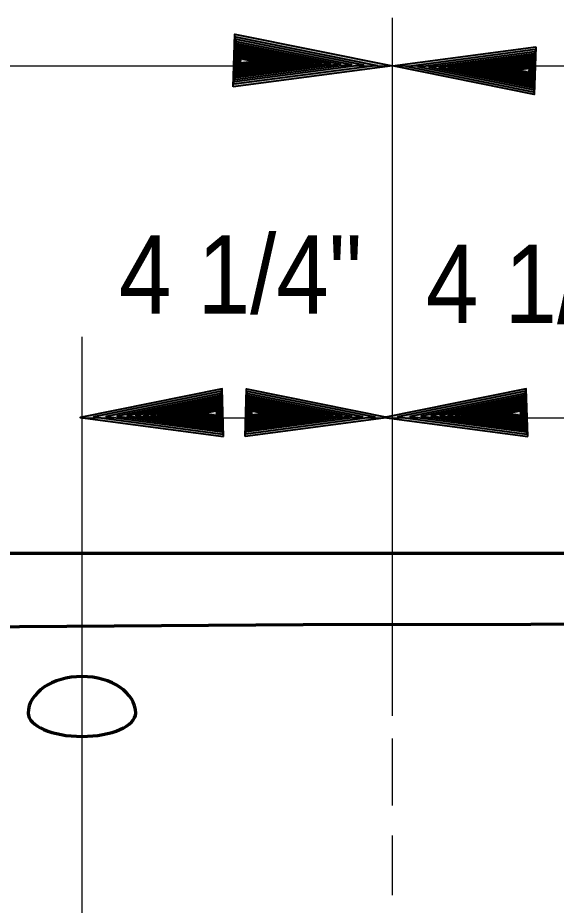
# Model space of a CAD drawing. Extents: x 895.6 to 930.4, y -2278.6 to -2254.7.
# Drawn here: x 917.544 to 918.427, y -2271.618 to -2270.162 of the extents above; entities that cross this region are included whole.
import ezdxf

# ---------------------------------------------------------------- set-up
doc = ezdxf.new("R2010")
doc.units = 0
doc.header["$LTSCALE"] = 0.051
doc.layers.add('1', color=7, linetype='Continuous', lineweight=70)
doc.layers.add('3', color=7, linetype='Continuous', lineweight=40)

msp = doc.modelspace()

# ---------------------------------------------------------------- hatches: boundary and pattern name
at = {"layer": '3'}
for points in [[(917.89717, -2270.27517), (917.90008, -2270.1885), (918.1585, -2270.24067), (918.1585, -2270.24067)], [(917.89842, -2270.27083), (917.90117, -2270.19283), (918.13367, -2270.23983), (918.13367, -2270.23983)], [(917.89967, -2270.26692), (917.902, -2270.19683), (918.11133, -2270.23917), (918.11133, -2270.23917)], [(917.90067, -2270.2635), (917.90283, -2270.20042), (918.09133, -2270.23842), (918.09133, -2270.23842)], [(917.90158, -2270.2605), (917.9035, -2270.20367), (918.07325, -2270.23783), (918.07325, -2270.23783)], [(917.90267, -2270.25758), (917.90425, -2270.2065), (918.057, -2270.23733), (918.057, -2270.23733)], [(917.90333, -2270.255), (917.90483, -2270.20908), (918.04225, -2270.23683), (918.04225, -2270.23683)], [(917.90417, -2270.25283), (917.90542, -2270.21142), (918.029, -2270.23633), (918.029, -2270.23633)], [(917.90458, -2270.25083), (917.90592, -2270.21342), (918.01725, -2270.23583), (918.01725, -2270.23583)], [(917.90533, -2270.24892), (917.90642, -2270.21517), (918.00642, -2270.2355), (918.00642, -2270.2355)], [(917.90575, -2270.24733), (917.90683, -2270.217), (917.99683, -2270.23525), (917.99683, -2270.23525)], [(917.90625, -2270.24575), (917.90717, -2270.21858), (917.98817, -2270.23483), (917.98817, -2270.23483)], [(917.90667, -2270.24442), (917.9075, -2270.21992), (917.98033, -2270.23467), (917.98033, -2270.23467)], [(918.39375, -2270.20958), (918.39108, -2270.28758), (918.1585, -2270.24067), (918.1585, -2270.24067)], [(918.39258, -2270.2135), (918.39017, -2270.28367), (918.18083, -2270.2415), (918.18083, -2270.2415)], [(918.3915, -2270.217), (918.38933, -2270.28017), (918.20092, -2270.24208), (918.20092, -2270.24208)], [(918.39058, -2270.22008), (918.38858, -2270.27683), (918.219, -2270.24267), (918.219, -2270.24267)], [(917.90717, -2270.24317), (917.90775, -2270.22117), (917.97342, -2270.23442), (917.97342, -2270.23442)], [(917.90742, -2270.24217), (917.90808, -2270.22225), (917.96717, -2270.23425), (917.96717, -2270.23425)], [(917.90783, -2270.24108), (917.90825, -2270.22325), (917.9615, -2270.23392), (917.9615, -2270.23392)], [(917.908, -2270.24017), (917.90858, -2270.22408), (917.95642, -2270.23375), (917.95642, -2270.23375)], [(917.90817, -2270.23933), (917.90867, -2270.22492), (917.95183, -2270.23358), (917.95183, -2270.23358)], [(917.90858, -2270.23892), (917.90883, -2270.22575), (917.94775, -2270.23358), (917.94775, -2270.23358)], [(917.90875, -2270.23833), (917.90917, -2270.2265), (917.94408, -2270.2335), (917.94408, -2270.2335)], [(917.90908, -2270.23783), (917.90942, -2270.22725), (917.94083, -2270.23367), (917.94083, -2270.23367)], [(917.90908, -2270.23725), (917.90942, -2270.22783), (917.93775, -2270.2335), (917.93775, -2270.2335)], [(917.90925, -2270.23675), (917.90958, -2270.22825), (917.935, -2270.23325), (917.935, -2270.23325)], [(917.90942, -2270.23633), (917.90967, -2270.22875), (917.93267, -2270.23333), (917.93267, -2270.23333)], [(918.38975, -2270.22275), (918.388, -2270.274), (918.23525, -2270.24317), (918.23525, -2270.24317)], [(918.38883, -2270.2255), (918.38733, -2270.27142), (918.24992, -2270.24375), (918.24992, -2270.24375)], [(918.38817, -2270.22775), (918.38683, -2270.26917), (918.26308, -2270.24417), (918.26308, -2270.24417)], [(918.38742, -2270.22967), (918.38633, -2270.267), (918.27508, -2270.2445), (918.27508, -2270.2445)], [(918.38708, -2270.23158), (918.38583, -2270.26525), (918.28567, -2270.24508), (918.28567, -2270.24508)], [(918.38642, -2270.23325), (918.38533, -2270.26358), (918.29542, -2270.24525), (918.29542, -2270.24525)], [(918.38592, -2270.23475), (918.38508, -2270.26192), (918.30408, -2270.24558), (918.30408, -2270.24558)], [(918.38558, -2270.23617), (918.38467, -2270.26058), (918.31175, -2270.24592), (918.31175, -2270.24592)], [(918.38517, -2270.23725), (918.38442, -2270.25933), (918.31892, -2270.24608), (918.31892, -2270.24608)], [(918.38467, -2270.23842), (918.38425, -2270.25825), (918.32508, -2270.24633), (918.32508, -2270.24633)], [(918.3845, -2270.23933), (918.38383, -2270.25725), (918.33075, -2270.24642), (918.33075, -2270.24642)], [(918.38417, -2270.24033), (918.38375, -2270.25642), (918.33583, -2270.24675), (918.33583, -2270.24675)], [(918.38392, -2270.24108), (918.3835, -2270.25567), (918.34042, -2270.24692), (918.34042, -2270.24692)], [(918.38383, -2270.24183), (918.38333, -2270.25483), (918.34458, -2270.24708), (918.34458, -2270.24708)], [(918.3835, -2270.24225), (918.38317, -2270.25408), (918.34817, -2270.24708), (918.34817, -2270.24708)], [(918.38325, -2270.24283), (918.38292, -2270.25342), (918.35142, -2270.24708), (918.35142, -2270.24708)], [(918.383, -2270.24317), (918.38267, -2270.25275), (918.35442, -2270.247), (918.35442, -2270.247)], [(918.383, -2270.24375), (918.38267, -2270.25225), (918.35725, -2270.24708), (918.35725, -2270.24708)], [(918.38283, -2270.24425), (918.3825, -2270.25183), (918.35958, -2270.24733), (918.35958, -2270.24733)], [(918.38267, -2270.2445), (918.3825, -2270.25133), (918.36183, -2270.24725), (918.36183, -2270.24725)], [(917.88167, -2270.84892), (917.879, -2270.77092), (917.64633, -2270.81783), (917.64633, -2270.81783)], [(917.91675, -2270.84892), (917.91942, -2270.77092), (918.15208, -2270.81783), (918.15208, -2270.81783)], [(918.38042, -2270.84892), (918.37775, -2270.77092), (918.14508, -2270.81783), (918.14508, -2270.81783)], [(917.88042, -2270.845), (917.87808, -2270.77483), (917.66875, -2270.817), (917.66875, -2270.817)], [(917.87942, -2270.8415), (917.87725, -2270.77842), (917.68883, -2270.81642), (917.68883, -2270.81642)], [(917.87842, -2270.83842), (917.8765, -2270.78167), (917.70692, -2270.81583), (917.70692, -2270.81583)], [(917.87767, -2270.83575), (917.87583, -2270.78458), (917.72317, -2270.81533), (917.72317, -2270.81533)], [(917.87667, -2270.83308), (917.87517, -2270.78708), (917.73783, -2270.81483), (917.73783, -2270.81483)], [(917.918, -2270.845), (917.92033, -2270.77483), (918.12967, -2270.817), (918.12967, -2270.817)], [(917.919, -2270.8415), (917.92117, -2270.77842), (918.10958, -2270.81642), (918.10958, -2270.81642)], [(917.92, -2270.83842), (917.92192, -2270.78167), (918.0915, -2270.81583), (918.0915, -2270.81583)], [(917.92075, -2270.83575), (917.92258, -2270.78458), (918.07525, -2270.81533), (918.07525, -2270.81533)], [(917.92175, -2270.83308), (917.92325, -2270.78708), (918.06058, -2270.81483), (918.06058, -2270.81483)], [(918.37917, -2270.845), (918.37683, -2270.77483), (918.1675, -2270.817), (918.1675, -2270.817)], [(918.37817, -2270.8415), (918.376, -2270.77842), (918.18758, -2270.81642), (918.18758, -2270.81642)], [(918.37717, -2270.83842), (918.37525, -2270.78167), (918.20567, -2270.81583), (918.20567, -2270.81583)], [(918.37642, -2270.83575), (918.37458, -2270.78458), (918.22192, -2270.81533), (918.22192, -2270.81533)], [(918.37542, -2270.83308), (918.37392, -2270.78708), (918.23658, -2270.81483), (918.23658, -2270.81483)], [(917.87608, -2270.83075), (917.87475, -2270.78933), (917.751, -2270.81433), (917.751, -2270.81433)], [(917.87533, -2270.82883), (917.87425, -2270.7915), (917.763, -2270.814), (917.763, -2270.814)], [(917.875, -2270.827), (917.87367, -2270.79333), (917.77358, -2270.8135), (917.77358, -2270.8135)], [(917.87433, -2270.82525), (917.87325, -2270.79492), (917.78325, -2270.81325), (917.78325, -2270.81325)], [(917.87383, -2270.82375), (917.87292, -2270.79658), (917.79192, -2270.81292), (917.79192, -2270.81292)], [(917.8735, -2270.82233), (917.87258, -2270.798), (917.79967, -2270.81258), (917.79967, -2270.81258)], [(917.873, -2270.82125), (917.87233, -2270.79917), (917.80683, -2270.81242), (917.80683, -2270.81242)], [(917.87258, -2270.82008), (917.87208, -2270.80025), (917.81292, -2270.81225), (917.81292, -2270.81225)], [(917.87233, -2270.81917), (917.87175, -2270.80125), (917.81867, -2270.81208), (917.81867, -2270.81208)], [(917.87208, -2270.81825), (917.87167, -2270.80208), (917.82375, -2270.81175), (917.82375, -2270.81175)], [(917.92233, -2270.83075), (917.92367, -2270.78933), (918.04742, -2270.81433), (918.04742, -2270.81433)], [(917.92308, -2270.82883), (917.92417, -2270.7915), (918.03542, -2270.814), (918.03542, -2270.814)], [(917.92342, -2270.827), (917.92475, -2270.79333), (918.02483, -2270.8135), (918.02483, -2270.8135)], [(917.92408, -2270.82525), (917.92517, -2270.79492), (918.01517, -2270.81325), (918.01517, -2270.81325)], [(917.92458, -2270.82375), (917.9255, -2270.79658), (918.0065, -2270.81292), (918.0065, -2270.81292)], [(917.92492, -2270.82233), (917.92583, -2270.798), (917.99875, -2270.81258), (917.99875, -2270.81258)], [(917.92542, -2270.82125), (917.92608, -2270.79917), (917.99158, -2270.81242), (917.99158, -2270.81242)], [(917.92583, -2270.82008), (917.92633, -2270.80025), (917.9855, -2270.81225), (917.9855, -2270.81225)], [(917.92608, -2270.81917), (917.92667, -2270.80125), (917.97975, -2270.81208), (917.97975, -2270.81208)], [(917.92633, -2270.81825), (917.92675, -2270.80208), (917.97467, -2270.81175), (917.97467, -2270.81175)], [(918.37483, -2270.83075), (918.3735, -2270.78933), (918.24975, -2270.81433), (918.24975, -2270.81433)], [(918.37408, -2270.82883), (918.373, -2270.7915), (918.26175, -2270.814), (918.26175, -2270.814)], [(918.37375, -2270.827), (918.37242, -2270.79333), (918.27233, -2270.8135), (918.27233, -2270.8135)], [(918.37308, -2270.82525), (918.372, -2270.79492), (918.282, -2270.81325), (918.282, -2270.81325)], [(918.37258, -2270.82375), (918.37167, -2270.79658), (918.29067, -2270.81292), (918.29067, -2270.81292)], [(918.37225, -2270.82233), (918.37133, -2270.798), (918.29842, -2270.81258), (918.29842, -2270.81258)], [(918.37175, -2270.82125), (918.37108, -2270.79917), (918.30558, -2270.81242), (918.30558, -2270.81242)], [(918.37133, -2270.82008), (918.37083, -2270.80025), (918.31167, -2270.81225), (918.31167, -2270.81225)], [(918.37108, -2270.81917), (918.3705, -2270.80125), (918.31742, -2270.81208), (918.31742, -2270.81208)], [(918.37083, -2270.81825), (918.37042, -2270.80208), (918.3225, -2270.81175), (918.3225, -2270.81175)], [(917.87183, -2270.81742), (917.87133, -2270.80283), (917.82833, -2270.81158), (917.82833, -2270.81158)], [(917.87167, -2270.81667), (917.87125, -2270.80367), (917.83242, -2270.8115), (917.83242, -2270.8115)], [(917.87133, -2270.81625), (917.87108, -2270.80442), (917.83608, -2270.8115), (917.83608, -2270.8115)], [(917.87117, -2270.81567), (917.87083, -2270.80508), (917.83933, -2270.81142), (917.83933, -2270.81142)], [(917.87092, -2270.81533), (917.87058, -2270.80575), (917.84233, -2270.81158), (917.84233, -2270.81158)], [(917.87092, -2270.81475), (917.87058, -2270.80625), (917.84508, -2270.81142), (917.84508, -2270.81142)], [(917.87075, -2270.81425), (917.87042, -2270.80667), (917.8475, -2270.81117), (917.8475, -2270.81117)], [(917.87058, -2270.814), (917.87033, -2270.80717), (917.84967, -2270.81125), (917.84967, -2270.81125)], [(917.92658, -2270.81742), (917.92708, -2270.80283), (917.97008, -2270.81158), (917.97008, -2270.81158)], [(917.92675, -2270.81667), (917.92717, -2270.80367), (917.966, -2270.8115), (917.966, -2270.8115)], [(917.92708, -2270.81625), (917.92733, -2270.80442), (917.96233, -2270.8115), (917.96233, -2270.8115)], [(917.92725, -2270.81567), (917.92758, -2270.80508), (917.95908, -2270.81142), (917.95908, -2270.81142)], [(917.9275, -2270.81533), (917.92783, -2270.80575), (917.95608, -2270.81158), (917.95608, -2270.81158)], [(917.9275, -2270.81475), (917.92783, -2270.80625), (917.95333, -2270.81142), (917.95333, -2270.81142)], [(917.92767, -2270.81425), (917.928, -2270.80667), (917.95092, -2270.81117), (917.95092, -2270.81117)], [(917.92783, -2270.814), (917.92808, -2270.80717), (917.94875, -2270.81125), (917.94875, -2270.81125)], [(918.37058, -2270.81742), (918.37008, -2270.80283), (918.32708, -2270.81158), (918.32708, -2270.81158)], [(918.37042, -2270.81667), (918.37, -2270.80367), (918.33117, -2270.8115), (918.33117, -2270.8115)], [(918.37008, -2270.81625), (918.36983, -2270.80442), (918.33483, -2270.8115), (918.33483, -2270.8115)], [(918.36992, -2270.81567), (918.36958, -2270.80508), (918.33808, -2270.81142), (918.33808, -2270.81142)], [(918.36967, -2270.81533), (918.36933, -2270.80575), (918.34108, -2270.81158), (918.34108, -2270.81158)], [(918.36967, -2270.81475), (918.36933, -2270.80625), (918.34383, -2270.81142), (918.34383, -2270.81142)], [(918.3695, -2270.81425), (918.36917, -2270.80667), (918.34625, -2270.81117), (918.34625, -2270.81117)], [(918.36933, -2270.814), (918.36908, -2270.80717), (918.34842, -2270.81125), (918.34842, -2270.81125)]]:
    msp.add_hatch(color=256, dxfattribs=at).paths.add_polyline_path(points)

# ---------------------------------------------------------------- linework, layer by layer
at = {"layer": '1', "lineweight": 25}
for p, q in [((918.1585, -2271.30775), (918.1585, -2270.16167)), ((915.22142, -2270.24067), (918.1585, -2270.24067)), ((918.1585, -2270.24067), (919.16992, -2270.24067)), ((917.64958, -2271.94067), (917.64958, -2270.68567)), ((917.64958, -2270.81817), (919.1535, -2270.81817)), ((918.1585, -2271.45492), (918.1585, -2271.34458)), ((918.1585, -2271.60208), (918.1585, -2271.504))]:
    msp.add_line(p, q, dxfattribs=at)
at = {"layer": '1'}
msp.add_line((919.14467, -2271.04083), (915.53433, -2271.04083), dxfattribs=at)
msp.add_lwpolyline([(919.14442, -2271.15792), (918.759, -2271.157), (918.012, -2271.15792), (917.23617, -2271.16342), (917.23658, -2271.1625)], dxfattribs=at)
for major_axis, ratio in [((-0.08819, 0), 0.679978), ((0.08819, 0), 0.434256)]:
    msp.add_ellipse((917.64926, -2271.30308), major_axis=major_axis, ratio=ratio, start_param=3.1415927, end_param=6.2831853, dxfattribs=at)
at = {"layer": '3'}
for points in [[(917.89717, -2270.27517), (917.90008, -2270.1885), (918.1585, -2270.24067), (918.1585, -2270.24067)], [(917.89842, -2270.27083), (917.90117, -2270.19283), (918.13367, -2270.23983), (918.13367, -2270.23983)], [(917.89967, -2270.26692), (917.902, -2270.19683), (918.11133, -2270.23917), (918.11133, -2270.23917)], [(917.90067, -2270.2635), (917.90283, -2270.20042), (918.09133, -2270.23842), (918.09133, -2270.23842)], [(917.90158, -2270.2605), (917.9035, -2270.20367), (918.07325, -2270.23783), (918.07325, -2270.23783)], [(917.90267, -2270.25758), (917.90425, -2270.2065), (918.057, -2270.23733), (918.057, -2270.23733)], [(917.90333, -2270.255), (917.90483, -2270.20908), (918.04225, -2270.23683), (918.04225, -2270.23683)], [(917.90417, -2270.25283), (917.90542, -2270.21142), (918.029, -2270.23633), (918.029, -2270.23633)], [(917.90458, -2270.25083), (917.90592, -2270.21342), (918.01725, -2270.23583), (918.01725, -2270.23583)], [(917.90533, -2270.24892), (917.90642, -2270.21517), (918.00642, -2270.2355), (918.00642, -2270.2355)], [(917.90575, -2270.24733), (917.90683, -2270.217), (917.99683, -2270.23525), (917.99683, -2270.23525)], [(917.90625, -2270.24575), (917.90717, -2270.21858), (917.98817, -2270.23483), (917.98817, -2270.23483)], [(917.90667, -2270.24442), (917.9075, -2270.21992), (917.98033, -2270.23467), (917.98033, -2270.23467)], [(918.39375, -2270.20958), (918.39108, -2270.28758), (918.1585, -2270.24067), (918.1585, -2270.24067)], [(918.39258, -2270.2135), (918.39017, -2270.28367), (918.18083, -2270.2415), (918.18083, -2270.2415)], [(918.3915, -2270.217), (918.38933, -2270.28017), (918.20092, -2270.24208), (918.20092, -2270.24208)], [(918.39058, -2270.22008), (918.38858, -2270.27683), (918.219, -2270.24267), (918.219, -2270.24267)], [(917.90717, -2270.24317), (917.90775, -2270.22117), (917.97342, -2270.23442), (917.97342, -2270.23442)], [(917.90742, -2270.24217), (917.90808, -2270.22225), (917.96717, -2270.23425), (917.96717, -2270.23425)], [(917.90783, -2270.24108), (917.90825, -2270.22325), (917.9615, -2270.23392), (917.9615, -2270.23392)], [(917.908, -2270.24017), (917.90858, -2270.22408), (917.95642, -2270.23375), (917.95642, -2270.23375)], [(917.90817, -2270.23933), (917.90867, -2270.22492), (917.95183, -2270.23358), (917.95183, -2270.23358)], [(917.90858, -2270.23892), (917.90883, -2270.22575), (917.94775, -2270.23358), (917.94775, -2270.23358)], [(917.90875, -2270.23833), (917.90917, -2270.2265), (917.94408, -2270.2335), (917.94408, -2270.2335)], [(917.90908, -2270.23783), (917.90942, -2270.22725), (917.94083, -2270.23367), (917.94083, -2270.23367)], [(917.90908, -2270.23725), (917.90942, -2270.22783), (917.93775, -2270.2335), (917.93775, -2270.2335)], [(917.90925, -2270.23675), (917.90958, -2270.22825), (917.935, -2270.23325), (917.935, -2270.23325)], [(917.90942, -2270.23633), (917.90967, -2270.22875), (917.93267, -2270.23333), (917.93267, -2270.23333)], [(918.38975, -2270.22275), (918.388, -2270.274), (918.23525, -2270.24317), (918.23525, -2270.24317)], [(918.38883, -2270.2255), (918.38733, -2270.27142), (918.24992, -2270.24375), (918.24992, -2270.24375)], [(918.38817, -2270.22775), (918.38683, -2270.26917), (918.26308, -2270.24417), (918.26308, -2270.24417)], [(918.38742, -2270.22967), (918.38633, -2270.267), (918.27508, -2270.2445), (918.27508, -2270.2445)], [(918.38708, -2270.23158), (918.38583, -2270.26525), (918.28567, -2270.24508), (918.28567, -2270.24508)], [(918.38642, -2270.23325), (918.38533, -2270.26358), (918.29542, -2270.24525), (918.29542, -2270.24525)], [(918.38592, -2270.23475), (918.38508, -2270.26192), (918.30408, -2270.24558), (918.30408, -2270.24558)], [(918.38558, -2270.23617), (918.38467, -2270.26058), (918.31175, -2270.24592), (918.31175, -2270.24592)], [(918.38517, -2270.23725), (918.38442, -2270.25933), (918.31892, -2270.24608), (918.31892, -2270.24608)], [(918.38467, -2270.23842), (918.38425, -2270.25825), (918.32508, -2270.24633), (918.32508, -2270.24633)], [(918.3845, -2270.23933), (918.38383, -2270.25725), (918.33075, -2270.24642), (918.33075, -2270.24642)], [(918.38417, -2270.24033), (918.38375, -2270.25642), (918.33583, -2270.24675), (918.33583, -2270.24675)], [(918.38392, -2270.24108), (918.3835, -2270.25567), (918.34042, -2270.24692), (918.34042, -2270.24692)], [(918.38383, -2270.24183), (918.38333, -2270.25483), (918.34458, -2270.24708), (918.34458, -2270.24708)], [(918.3835, -2270.24225), (918.38317, -2270.25408), (918.34817, -2270.24708), (918.34817, -2270.24708)], [(918.38325, -2270.24283), (918.38292, -2270.25342), (918.35142, -2270.24708), (918.35142, -2270.24708)], [(918.383, -2270.24317), (918.38267, -2270.25275), (918.35442, -2270.247), (918.35442, -2270.247)], [(918.383, -2270.24375), (918.38267, -2270.25225), (918.35725, -2270.24708), (918.35725, -2270.24708)], [(918.38283, -2270.24425), (918.3825, -2270.25183), (918.35958, -2270.24733), (918.35958, -2270.24733)], [(918.38267, -2270.2445), (918.3825, -2270.25133), (918.36183, -2270.24725), (918.36183, -2270.24725)], [(917.88167, -2270.84892), (917.879, -2270.77092), (917.64633, -2270.81783), (917.64633, -2270.81783)], [(917.91675, -2270.84892), (917.91942, -2270.77092), (918.15208, -2270.81783), (918.15208, -2270.81783)], [(918.38042, -2270.84892), (918.37775, -2270.77092), (918.14508, -2270.81783), (918.14508, -2270.81783)], [(917.88042, -2270.845), (917.87808, -2270.77483), (917.66875, -2270.817), (917.66875, -2270.817)], [(917.87942, -2270.8415), (917.87725, -2270.77842), (917.68883, -2270.81642), (917.68883, -2270.81642)], [(917.87842, -2270.83842), (917.8765, -2270.78167), (917.70692, -2270.81583), (917.70692, -2270.81583)], [(917.87767, -2270.83575), (917.87583, -2270.78458), (917.72317, -2270.81533), (917.72317, -2270.81533)], [(917.87667, -2270.83308), (917.87517, -2270.78708), (917.73783, -2270.81483), (917.73783, -2270.81483)], [(917.918, -2270.845), (917.92033, -2270.77483), (918.12967, -2270.817), (918.12967, -2270.817)], [(917.919, -2270.8415), (917.92117, -2270.77842), (918.10958, -2270.81642), (918.10958, -2270.81642)], [(917.92, -2270.83842), (917.92192, -2270.78167), (918.0915, -2270.81583), (918.0915, -2270.81583)], [(917.92075, -2270.83575), (917.92258, -2270.78458), (918.07525, -2270.81533), (918.07525, -2270.81533)], [(917.92175, -2270.83308), (917.92325, -2270.78708), (918.06058, -2270.81483), (918.06058, -2270.81483)], [(918.37917, -2270.845), (918.37683, -2270.77483), (918.1675, -2270.817), (918.1675, -2270.817)], [(918.37817, -2270.8415), (918.376, -2270.77842), (918.18758, -2270.81642), (918.18758, -2270.81642)], [(918.37717, -2270.83842), (918.37525, -2270.78167), (918.20567, -2270.81583), (918.20567, -2270.81583)], [(918.37642, -2270.83575), (918.37458, -2270.78458), (918.22192, -2270.81533), (918.22192, -2270.81533)], [(918.37542, -2270.83308), (918.37392, -2270.78708), (918.23658, -2270.81483), (918.23658, -2270.81483)], [(917.87608, -2270.83075), (917.87475, -2270.78933), (917.751, -2270.81433), (917.751, -2270.81433)], [(917.87533, -2270.82883), (917.87425, -2270.7915), (917.763, -2270.814), (917.763, -2270.814)], [(917.875, -2270.827), (917.87367, -2270.79333), (917.77358, -2270.8135), (917.77358, -2270.8135)], [(917.87433, -2270.82525), (917.87325, -2270.79492), (917.78325, -2270.81325), (917.78325, -2270.81325)], [(917.87383, -2270.82375), (917.87292, -2270.79658), (917.79192, -2270.81292), (917.79192, -2270.81292)], [(917.8735, -2270.82233), (917.87258, -2270.798), (917.79967, -2270.81258), (917.79967, -2270.81258)], [(917.873, -2270.82125), (917.87233, -2270.79917), (917.80683, -2270.81242), (917.80683, -2270.81242)], [(917.87258, -2270.82008), (917.87208, -2270.80025), (917.81292, -2270.81225), (917.81292, -2270.81225)], [(917.87233, -2270.81917), (917.87175, -2270.80125), (917.81867, -2270.81208), (917.81867, -2270.81208)], [(917.87208, -2270.81825), (917.87167, -2270.80208), (917.82375, -2270.81175), (917.82375, -2270.81175)], [(917.92233, -2270.83075), (917.92367, -2270.78933), (918.04742, -2270.81433), (918.04742, -2270.81433)], [(917.92308, -2270.82883), (917.92417, -2270.7915), (918.03542, -2270.814), (918.03542, -2270.814)], [(917.92342, -2270.827), (917.92475, -2270.79333), (918.02483, -2270.8135), (918.02483, -2270.8135)], [(917.92408, -2270.82525), (917.92517, -2270.79492), (918.01517, -2270.81325), (918.01517, -2270.81325)], [(917.92458, -2270.82375), (917.9255, -2270.79658), (918.0065, -2270.81292), (918.0065, -2270.81292)], [(917.92492, -2270.82233), (917.92583, -2270.798), (917.99875, -2270.81258), (917.99875, -2270.81258)], [(917.92542, -2270.82125), (917.92608, -2270.79917), (917.99158, -2270.81242), (917.99158, -2270.81242)], [(917.92583, -2270.82008), (917.92633, -2270.80025), (917.9855, -2270.81225), (917.9855, -2270.81225)], [(917.92608, -2270.81917), (917.92667, -2270.80125), (917.97975, -2270.81208), (917.97975, -2270.81208)], [(917.92633, -2270.81825), (917.92675, -2270.80208), (917.97467, -2270.81175), (917.97467, -2270.81175)], [(918.37483, -2270.83075), (918.3735, -2270.78933), (918.24975, -2270.81433), (918.24975, -2270.81433)], [(918.37408, -2270.82883), (918.373, -2270.7915), (918.26175, -2270.814), (918.26175, -2270.814)], [(918.37375, -2270.827), (918.37242, -2270.79333), (918.27233, -2270.8135), (918.27233, -2270.8135)], [(918.37308, -2270.82525), (918.372, -2270.79492), (918.282, -2270.81325), (918.282, -2270.81325)], [(918.37258, -2270.82375), (918.37167, -2270.79658), (918.29067, -2270.81292), (918.29067, -2270.81292)], [(918.37225, -2270.82233), (918.37133, -2270.798), (918.29842, -2270.81258), (918.29842, -2270.81258)], [(918.37175, -2270.82125), (918.37108, -2270.79917), (918.30558, -2270.81242), (918.30558, -2270.81242)], [(918.37133, -2270.82008), (918.37083, -2270.80025), (918.31167, -2270.81225), (918.31167, -2270.81225)], [(918.37108, -2270.81917), (918.3705, -2270.80125), (918.31742, -2270.81208), (918.31742, -2270.81208)], [(918.37083, -2270.81825), (918.37042, -2270.80208), (918.3225, -2270.81175), (918.3225, -2270.81175)], [(917.87183, -2270.81742), (917.87133, -2270.80283), (917.82833, -2270.81158), (917.82833, -2270.81158)], [(917.87167, -2270.81667), (917.87125, -2270.80367), (917.83242, -2270.8115), (917.83242, -2270.8115)], [(917.87133, -2270.81625), (917.87108, -2270.80442), (917.83608, -2270.8115), (917.83608, -2270.8115)], [(917.87117, -2270.81567), (917.87083, -2270.80508), (917.83933, -2270.81142), (917.83933, -2270.81142)], [(917.87092, -2270.81533), (917.87058, -2270.80575), (917.84233, -2270.81158), (917.84233, -2270.81158)], [(917.87092, -2270.81475), (917.87058, -2270.80625), (917.84508, -2270.81142), (917.84508, -2270.81142)], [(917.87075, -2270.81425), (917.87042, -2270.80667), (917.8475, -2270.81117), (917.8475, -2270.81117)], [(917.87058, -2270.814), (917.87033, -2270.80717), (917.84967, -2270.81125), (917.84967, -2270.81125)], [(917.92658, -2270.81742), (917.92708, -2270.80283), (917.97008, -2270.81158), (917.97008, -2270.81158)], [(917.92675, -2270.81667), (917.92717, -2270.80367), (917.966, -2270.8115), (917.966, -2270.8115)], [(917.92708, -2270.81625), (917.92733, -2270.80442), (917.96233, -2270.8115), (917.96233, -2270.8115)], [(917.92725, -2270.81567), (917.92758, -2270.80508), (917.95908, -2270.81142), (917.95908, -2270.81142)], [(917.9275, -2270.81533), (917.92783, -2270.80575), (917.95608, -2270.81158), (917.95608, -2270.81158)], [(917.9275, -2270.81475), (917.92783, -2270.80625), (917.95333, -2270.81142), (917.95333, -2270.81142)], [(917.92767, -2270.81425), (917.928, -2270.80667), (917.95092, -2270.81117), (917.95092, -2270.81117)], [(917.92783, -2270.814), (917.92808, -2270.80717), (917.94875, -2270.81125), (917.94875, -2270.81125)], [(918.37058, -2270.81742), (918.37008, -2270.80283), (918.32708, -2270.81158), (918.32708, -2270.81158)], [(918.37042, -2270.81667), (918.37, -2270.80367), (918.33117, -2270.8115), (918.33117, -2270.8115)], [(918.37008, -2270.81625), (918.36983, -2270.80442), (918.33483, -2270.8115), (918.33483, -2270.8115)], [(918.36992, -2270.81567), (918.36958, -2270.80508), (918.33808, -2270.81142), (918.33808, -2270.81142)], [(918.36967, -2270.81533), (918.36933, -2270.80575), (918.34108, -2270.81158), (918.34108, -2270.81158)], [(918.36967, -2270.81475), (918.36933, -2270.80625), (918.34383, -2270.81142), (918.34383, -2270.81142)], [(918.3695, -2270.81425), (918.36917, -2270.80667), (918.34625, -2270.81117), (918.34625, -2270.81117)], [(918.36933, -2270.814), (918.36908, -2270.80717), (918.34842, -2270.81125), (918.34842, -2270.81125)]]:
    msp.add_lwpolyline(points, close=True, dxfattribs=at)

# ---------------------------------------------------------------- texts
at = {"layer": '1', "width": 0.9}
for p in [(917.70992, -2270.64733), (918.21333, -2270.66283)]:
    msp.add_text('4 1/4"', height=0.1286, dxfattribs=at).set_placement(p)

doc.saveas('drawing.dxf')
